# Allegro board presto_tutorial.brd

Outline 100 x 50 mm; copper layers: TOP, POWERPLANE_1, BOTTOM. Coordinates in mm from the lower left corner of the outline.
Outline path: 0,50 100,50 100,0 0,0 0,50

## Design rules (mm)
constraint set DEFAULT: min track width 0.127
net group DPD: nets D+ D-

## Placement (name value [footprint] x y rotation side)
C1  10uF  [0402-CAP]  12.95 37.08 270 top
C2  100uF  [1210]  6.86 32.51 0 top
C3  10uF  [0402-CAP]  35.05 26.67 180 top
C4  0.1uF  [0402-CAP]  32.62 18.29 0 top
C5  0.1uF  [0402-CAP]  32.62 17.12 0 top
C6  0.1uF  [0402-CAP]  32.62 15.95 0 top
C7  0.1uF  [0402-CAP]  32.62 14.78 0 top
C8  0.1uF  [0402-CAP]  32.62 13.61 0 top
C9  10uF  [0402-CAP]  10.16 22.35 180 top
IC1  PIC32MX440F512H  [SQFP-S-10X10-64]  20.83 25.91 90 top
JP1  -  [XTEND-DIGI-MODEM]  68.75 24.68 0 top
JP2  PIC 32 PROG  [1X06_LOCK]  13.21 7.62 0 top
MAIN_PWR  LED  [LED_LNJ]  4.83 27.69 0 top
NOREF  -  []  0 0 0 top
NOREF#2  -  [unnamed#2]  96 4 0 top
NOREF#3  -  []  0 0 0 top
NOREF#4  -  [unnamed#2]  4 4 0 top
NOREF#5  -  [unnamed#2]  96 46 0 top
NOREF#6  -  [unnamed#2]  4 46 0 top
R1  150  [0402-RES]  9.29 27.69 180 top
R2  56k  [0402-RES]  35.05 24.64 180 top
U1  LT1965EMS8E-1P5  [MSOP_8_ADI]  6.86 37.34 0 top
X1  USB-B  [USB-MICROB]  20 46 180 top
Y1  8MHz  [CRYSTAL-SMD]  19.49 37.22 270 top

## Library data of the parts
C1-C3 C9 = CAP NP
C4-C8 = CAP NP: room: PWR_3.3V
IC1 = PIC32MX440F512H
JP1 = XTEND-DIGI-MODEM
JP2 = M06_LOCK
MAIN_PWR = LED: Tolerance: TOL
R1 R2 = RESISTOR
U1 = LT1965EMS8E-1P5_1: User Part Number: PN; Tolerance: TOL
X1 = USB-MICROB
Y1 = CRYSTAL

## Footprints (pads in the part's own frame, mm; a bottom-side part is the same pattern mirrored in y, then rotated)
1X06_LOCK
  rect 1.651x1.651 hole 0.914: 1(0,0)
  round 1.88 hole 1.016: 2(2.54,-0.254) 3(5.08,0) 4(7.62,-0.254) 5(10.16,0) 6(12.7,-0.254)
0402-CAP
  rect 0.7x0.9 smd: 1(-0.65,0) 2(0.65,0)
0402-RES
  rect 0.7x0.9 smd: 1(-0.65,0) 2(0.65,0)
1210
  rect 1.2x2 smd: 1(-1.6,0) 2(1.6,0)
CRYSTAL-SMD
  rect 1.1x1.9 smd: 1(-1.15,1.85) 2(-1.15,-1.85) 3(1.15,-1.85) 4(1.15,1.85)
LED_LNJ
  rect 0.445x0.95 smd: 1(-0.652,0) 2(0.652,0)
MSOP_8_ADI
  rect 1.31x0.431 smd: 1(-2.235,0.975) 2(-2.235,0.325) 3(-2.235,-0.325) 4(-2.235,-0.975) 5(2.235,-0.975) 6(2.235,-0.325) 7(2.235,0.325) 8(2.235,0.975)
SQFP-S-10X10-64
  rect 1.6x0.295 smd: 1(-5.6,3.75) 2(-5.6,3.25) 3(-5.6,2.75) 4(-5.6,2.25) 5(-5.6,1.75) 6(-5.6,1.25) 7(-5.6,0.75) 8(-5.6,0.25) 9(-5.6,-0.25) 10(-5.6,-0.75) 11(-5.6,-1.25) 12(-5.6,-1.75) 13(-5.6,-2.25) 14(-5.6,-2.75) 15(-5.6,-3.25) 16(-5.6,-3.75) 33(5.6,-3.75) 34(5.6,-3.25) 35(5.6,-2.75) 36(5.6,-2.25) 37(5.6,-1.75) 38(5.6,-1.25) 39(5.6,-0.75) 40(5.6,-0.25) 41(5.6,0.25) 42(5.6,0.75) 43(5.6,1.25) 44(5.6,1.75) 45(5.6,2.25) 46(5.6,2.75) 47(5.6,3.25) 48(5.6,3.75)
  rect 0.295x1.6 smd: 17(-3.75,-5.6) 18(-3.25,-5.6) 19(-2.75,-5.6) 20(-2.25,-5.6) 21(-1.75,-5.6) 22(-1.25,-5.6) 23(-0.75,-5.6) 24(-0.25,-5.6) 25(0.25,-5.6) 26(0.75,-5.6) 27(1.25,-5.6) 28(1.75,-5.6) 29(2.25,-5.6) 30(2.75,-5.6) 31(3.25,-5.6) 32(3.75,-5.6) 49(3.75,5.6) 50(3.25,5.6) 51(2.75,5.6) 52(2.25,5.6) 53(1.75,5.6) 54(1.25,5.6) 55(0.75,5.6) 56(0.25,5.6) 57(-0.25,5.6) 58(-0.75,5.6) 59(-1.25,5.6) 60(-1.75,5.6) 61(-2.25,5.6) 62(-2.75,5.6) 63(-3.25,5.6) 64(-3.75,5.6)
unnamed#2
  round 4.064 hole 3.81: (0,0)
USB-MICROB
  rect 0.35x1.4 smd: D+(0,2.65) D-(-0.65,2.65) GND(1.3,2.65) ID(0.65,2.65) VBUS(-1.3,2.65)
  rect 1.8x1.9 smd: MT1(-3.8,0) MT2(3.8,0)
  rect 2.1x1.6 smd: MT3(-3.1,2.55) MT4(3.1,2.55)
  rect 1.9x1.9 smd: P_1(-1.2,0) P_2(1.2,0)
XTEND-DIGI-MODEM
  round 0 hole 3.3 unplated: (-26.5,14.5) (-26.5,-14.5) (26.5,14.5) (26.5,-14.5)
  round 1.422 hole 0.7: 1(-27.5,9) 2(-25.5,9) 3(-27.5,7) 4(-25.5,7) 5(-27.5,5) 6(-25.5,5) 7(-27.5,3) 8(-25.5,3) 9(-27.5,1) 10(-25.5,1) 11(-27.5,-1) 12(-25.5,-1) 13(-27.5,-3) 14(-25.5,-3) 15(-27.5,-5) 16(-25.5,-5) 17(-27.5,-7) 18(-25.5,-7) 19(-27.5,-9) 20(-25.5,-9)

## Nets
3.3V: C2.1 C4.1 C5.1 C6.1 C7.1 C8.1 IC1.10 IC1.19 IC1.26 IC1.35 IC1.38 JP2.2 R1.1 R2.2 U1.1 U1.2 U1.3(SENSE/ADJ*)
GND: C1.2 C2.2 C3.2 C4.2 C5.2 C6.2 C7.2 C8.2 C9.2 IC1.9 IC1.20 IC1.25 IC1.41 JP1.1 JP2.3 MAIN_PWR.1(CATHODE) U1.4 U1.5 X1.GND Y1.2 Y1.4(GND_4)
VBUS: C1.1 IC1.34 JP1.2(VCC) U1.6 U1.7 U1.8 X1.VBUS
CTS: IC1.21 JP1.9
D+: IC1.37 X1.D+
D-: IC1.36 X1.D-
PROG0: IC1.17 JP2.5
PROG1: IC1.18 JP2.4
RESET: IC1.7(_MCLR) JP2.1
RTS: IC1.29 JP1.10
SHDN: IC1.59 JP1.7
URX: IC1.31 JP1.6
UTX: IC1.32 JP1.5
N01899: MAIN_PWR.2 R1.2
N02098: IC1.39 Y1.1
N02102: IC1.40 Y1.3
N02114: C9.1 IC1.56
N02189: C3.1 JP1.11 R2.1

Pads without a net: IC1 1 2 3 4 5 6 8 11 12 13 14 15 16 22 23 24 27 28 30 33 42 43 44 45 46 47 48 49 50 51 52 53 54 55 57 58 60 61 62 63 64; JP1 3 4 8 12 13 14 15 16 17 18 19 20; JP2 6; X1 ID MT1 MT2 MT3 MT4 P_1 P_2
